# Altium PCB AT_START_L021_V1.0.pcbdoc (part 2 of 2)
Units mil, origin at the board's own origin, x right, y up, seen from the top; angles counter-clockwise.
Board outline 12992.58 x 3605 mil, 2 copper layers (Top Layer, Bottom Layer); 116 components, 109 nets, 471 pads, 502 vias.
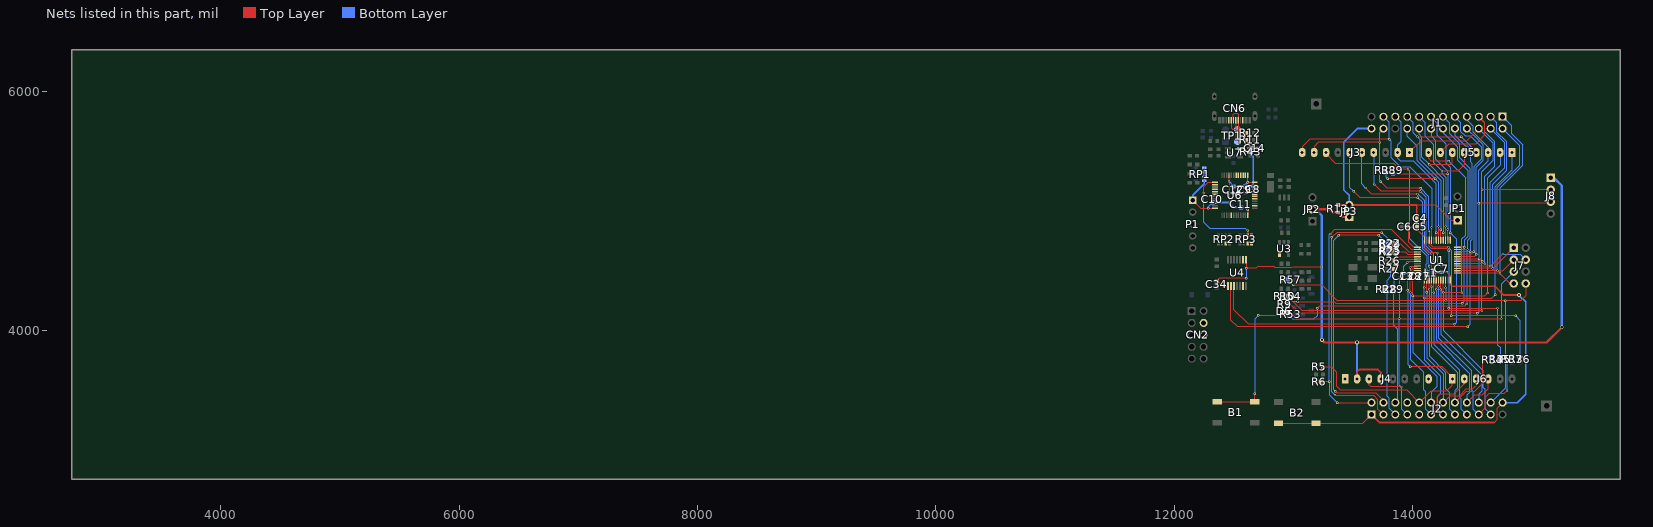
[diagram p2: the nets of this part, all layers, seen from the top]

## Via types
v1: diameter 19.68, hole 11.81, Top Layer to Bottom Layer, 217 vias
v2: diameter 19.7, hole 11.8, Top Layer to Bottom Layer, 181 vias
v3: diameter 19.7, hole 11.81, Top Layer to Bottom Layer, 91 vias
v4: diameter 31.5, hole 19.68, Top Layer to Bottom Layer, 13 vias

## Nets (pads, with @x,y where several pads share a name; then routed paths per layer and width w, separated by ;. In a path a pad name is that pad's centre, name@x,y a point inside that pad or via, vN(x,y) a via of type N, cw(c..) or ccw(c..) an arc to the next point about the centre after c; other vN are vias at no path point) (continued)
M_ATLK_SWO: RP3.6 U6.13 | length 844
  Top Layer w6: v1(12246.58,5152) 12246.58,5203 12285.12,5241.55 U6.13@12341.38,5241.55 ; RP3.6@12615.33,4798.44 12615.33,4837.75 v1(12615.58,4838)
  Bottom Layer w6: v1(12246.58,5152) 12246.58,4907 12300.58,4853 12600.58,4853 v1(12615.58,4838)
NRST: B1.1 B1.2 C13.2 D6.2 J2.7 J4.3 J7.5 U1.7 | length 5323.3
  Top Layer w6: B1.1@12360.5,3401.18 B1.2@12675.45,3401.18 12675.45,3467.12 v1(12674.58,3468) ; v1(12705.58,4126) 12905.58,4126 12941.58,4162 D6.2@12949.58,4162 12962.58,4162 13026.58,4098 13887.58,4098 v1(13888.58,4099) v1(14745.58,4099) ; J4.3@13633.35,3592.35 13633.35,3544.23 13652.58,3525 v1(13904.58,3525) ; v1(13955.58,4569) 13965.38,4578.8 U1.7@14039.67,4578.8
  Bottom Layer w6: v1(12674.58,3468) 12674.58,4095 v1(12705.58,4126) ; v1(13888.58,4099) 13888.58,4093.29 v1@13889.58,4092.29 ; J2.7@13954.61,3293.91 13904.58,3343.94 v1(13904.58,3525) 13889.58,3540 v1@13889.58,4092.29 ; v1(13955.58,4569) 13920.58,4534 C13.2@13920.58,4480.56 13889.58,4449.56 v1@13889.58,4092.29 ; v1(14745.58,4099) 14745.58,4390.12 J7.5@14848.35,4492.9
PA0: J2.10 J6.1 R5.2 U1.10 | length 2687.3
  Top Layer w6: R5.2@13246.24,3693 13317.58,3693 13358.58,3652 13358.58,3534 13392.58,3500 13948.52,3500 J2.10@14054.61,3393.91 14154.69,3494 14287.58,3494 14333.33,3539.76 J6.1@14333.33,3592.35 14333.33,3608.24 14246.58,3695 v1(13978.58,3695) ; v1(13957.58,4336) 13957.58,4472 14005.27,4519.7 U1.10@14039.67,4519.7
  Bottom Layer w6: v1(13957.58,4336) 13957.58,3716 v1(13978.58,3695)
PA1: J2.11 J6.2 U1.11 | length 1803.1
  Top Layer w6: v1(13981.58,4315) 13981.58,4475 14006.58,4500 U1.11@14039.67,4500 ; J2.11@14154.61,3293.91 14205.58,3344.88 14205.58,3442 14232.58,3469 14348.58,3469 14433.33,3553.76 J6.2@14433.33,3592.35
  Bottom Layer w6: v1(13981.58,4315) 13981.58,3759 14087.58,3653 14087.58,3506 14104.58,3489 14104.58,3343.94 J2.11@14154.61,3293.91
PA2: J2.12 J5.2 U1.12 | length 3078.3
  Top Layer w6: U1.12@14039.67,4480.3 14015.88,4480.3 14001.58,4466 v1(14001.58,4290) 14605.24,4290 v3(14628.58,4313.33)
  Bottom Layer w6: v1(14001.58,4290) 14001.58,3815 14202.58,3614 14202.58,3528 14154.61,3480.03 J2.12@14154.61,3393.91 ; v3(14628.58,4313.33) 14628.58,5280 14733.35,5384.78 J5.2@14733.35,5492.35
PA3: J2.13 J5.1 U1.13 | length 3072
  Top Layer w6: v3(14098.58,4271) 14664.58,4271 v1(14691.58,4298) ; v1(14098.58,4359) 14098.67,4359.1 U1.13@14098.67,4421.3
  Bottom Layer w6: v1(14098.58,4359) v3(14098.58,4271) 14098.58,3753 14231.58,3620 14231.58,3468 14204.58,3441 14204.58,3343.94 J2.13@14254.61,3293.91 ; v1(14691.58,4298) 14691.73,4297.84 14691.73,5206.16 14833.35,5347.78 J5.1@14833.35,5492.35
PA4: J2.14 J6.3 U1.14 | length 1476.8
  Top Layer w6: v1(14117.58,4319) 14118.38,4319.8 U1.14@14118.38,4421.3 ; J2.14@14254.61,3393.91 14309.69,3449 14389.98,3449 14449.63,3508.65 14503.23,3508.65 14533.33,3538.76 J6.3@14533.33,3592.35
  Bottom Layer w6: v1(14117.58,4319) 14117.58,3771 14254.61,3633.97 J2.14@14254.61,3393.91
PA5: J2.15 J3.6 U1.15 | length 2848
  Top Layer w6: v1(13504.58,5167) 13558.58,5113 v1(14043.58,5113) ; v1(14137.58,4342) 14138.08,4342.5 U1.15@14138.08,4421.3 14138.08,4537.5 v1(14137.58,4538)
  Bottom Layer w6: J3.6@13473.35,5492.35 13473.35,5198.23 v1(13504.58,5167) ; v1(14043.58,5113) 14083.58,5073 14083.58,4685 14137.58,4631 v1(14137.58,4538) ; v1(14137.58,4342) 14137.58,3786 14273.58,3650 14273.58,3514 14305.58,3482 14305.58,3342.94 J2.15@14354.61,3293.91
PA6: J2.16 J3.5 R34.1 U1.16 | length 3250.7
  Top Layer w6: v1(13607.58,5194) 13658.58,5143 v1(14040.58,5143) ; v1(14157.58,4365) 14157.77,4365.2 U1.16@14157.77,4421.3 14157.77,4559.8 v1(14157.58,4560) ; J2.16@14354.61,3393.91 14444.69,3484 14517.58,3484 14584.58,3551 14584.58,3730 v1(14619.58,3765)
  Bottom Layer w6: J3.5@13573.35,5492.35 13573.35,5228.23 v1(13607.58,5194) ; v1(14040.58,5143) 14048.58,5143 14098.58,5093 14098.58,4696 14157.58,4637 v1(14157.58,4560) ; v1(14157.58,4365) 14157.58,3868 14375.58,3650 14375.58,3512.55 14354.61,3491.58 J2.16@14354.61,3393.91 ; v1(14619.58,3765) 14639.24,3784.66 R34.1@14670.58,3784.66
PA7: J2.17 J3.4 U1.17 | length 2715
  Top Layer w6: v1(13677.58,5224) 13736.58,5165 v1(14064.58,5165) ; v1(14176.58,4318) 14177.48,4318.9 U1.17@14177.48,4421.3 14177.48,4582.9 v1(14177.58,4583)
  Bottom Layer w6: J3.4@13673.35,5492.35 13677.58,5488.13 v1(13677.58,5224) ; v1(14064.58,5165) 14114.58,5115 14114.58,4706 14177.58,4643 v1(14177.58,4583) ; v1(14176.58,4318) 14176.58,3885 14392.58,3669 14392.58,3442 14404.58,3430 14404.58,3343.94 J2.17@14454.61,3293.91
PA8: J1.5 J5.7 U1.29 | length 2160.1
  Top Layer w6: J5.7@14233.35,5492.35 14304,5563 14527.58,5563 14601.58,5637 14601.58,5745.12 J1.5@14554.6,5792.09 ; U1.29@14374.27,4559.1 14606.48,4559.1 v1(14606.58,4559)
  Bottom Layer w6: J1.5@14554.6,5792.09 14605.58,5741.12 14605.58,5665 14689.58,5581 14689.58,5377 14604.58,5292 14604.58,4561 v1(14606.58,4559)
PA9: J1.6 J3.1 J8.2 R10.2 U1.30 | length 4743.9
  Top Layer w6: R10.2@12955.58,4283 13073.58,4165 v1(14581.58,4165) ; J3.1@13973.35,5492.35 14065.99,5585 14447.5,5585 J1.6@14554.6,5692.09 ; U1.30@14374.27,4578.8 14582.38,4578.8 v1(14582.58,4579) ; v1(14581.58,5179) J8.2@15158.58,5179
  Bottom Layer w6: J1.6@14554.6,5692.09 14676.58,5570.12 14676.58,5427 14580.58,5331 v1@14580.58,5178.87 ; v1(14581.58,4165) 14581.58,4578 v1(14582.58,4579) 14580.58,4581 v1@14580.58,5178.87 ; v1(14581.58,5179) 14580.7,5179 v1@14580.58,5178.87
PA10: J1.7 J5.3 J8.3 R9.2 U1.31 | length 4178
  Top Layer w6: R9.2@12955.24,4220 12974.58,4220 13052.58,4142 v1(14541.58,4142) ; U1.31@14374.27,4598.4 14556.98,4598.4 v1(14557.58,4599) ; v1(14553.58,5066) 15145.58,5066 J8.3@15158.58,5079
  Bottom Layer w6: J1.7@14454.6,5792.09 14454.6,5765.98 14505.58,5715 14505.58,5664 14552.58,5617 14552.58,5615.5 14633.35,5534.72 J5.3@14633.35,5492.35 14633.35,5422.78 14553.58,5343 v1(14553.58,5066) 14557.58,5062 v1(14557.58,4599) 14557.58,4158 v1(14541.58,4142)
PA11: J1.8 U1.32 | length 1302.7
  Top Layer w6: U1.32@14374.27,4618.1 14515.67,4618.1 v1(14534.58,4637)
  Bottom Layer w6: J1.8@14454.6,5692.09 14548.58,5598.12 14548.58,5597 14590.58,5555 14590.58,5426 14534.73,5370.16 14534.73,4637.16 v1(14534.58,4637)
PA12: J1.9 U1.33 | length 1425.2
  Top Layer w6: U1.33@14374.27,4637.8 14492.38,4637.8 v1(14512.58,4658)
  Bottom Layer w6: J1.9@14354.6,5792.09 14403.58,5743.12 14403.58,5668 14444.58,5627 14487.58,5627 14577.58,5537 14577.58,5440 14515.58,5378 14515.58,4661 v1(14512.58,4658)
PA13/SWDIO: J1.10 U1.34 U4.2 | length 4152.1
  Top Layer w6: U4.2@12475.4,4371.76 12475.4,4086.18 12531.58,4030 v1(14463.58,4030) ; U1.34@14374.27,4657.5 14481.08,4657.5 v1(14482.58,4659)
  Bottom Layer w6: J1.10@14354.6,5692.09 14354.6,5634.98 14440.12,5549.45 14457.12,5549.45 14482.58,5524 14482.58,5418 14497.58,5403 14497.58,4761.4 14482.58,4746.4 v1(14482.58,4659) 14483.58,4658 14483.58,4050 v1(14463.58,4030)
PA14/SWCLK: J1.13 U1.37 U4.3 | length 3999.9
  Top Layer w6: U4.3@12500.99,4371.76 12500.99,4173.59 12624.58,4050 v1(14351.58,4050) ; U1.37@14315.27,4755.9 14315.27,4818.7 v1(14315.58,4819)
  Bottom Layer w6: J1.13@14154.6,5792.09 14203.58,5743.12 14203.58,5641 14277.58,5567 14277.58,5405 14315.58,5367 v1(14315.58,4819) 14316.58,4819 14366.58,4769 14366.58,4065 v1(14351.58,4050)
PA15: J1.14 R39.1 U1.38 | length 1456.1
  Top Layer w6: v1(13886.58,5312) v1(14295.58,5312) ; U1.38@14295.58,4755.9 v1(14295.58,4846)
  Bottom Layer w6: R39.1@13834.58,5313.34 13885.24,5313.34 v1(13886.58,5312) ; J1.14@14154.6,5692.09 14154.6,5632.09 14191.58,5595.11 14191.58,5439 14295.58,5335 v1(14295.58,5312) v1(14295.58,4846)
PB0: J2.18 J6.4 U1.18 | length 1461.2
  Top Layer w6: v1(14196.58,4342) 14197.17,4342.6 U1.18@14197.17,4421.3 ; J2.18@14454.61,3393.91 14520.69,3460 14583.58,3460 14633.33,3509.76 J6.4@14633.33,3592.35
  Bottom Layer w6: v1(14196.58,4342) 14196.58,3919 14475.58,3640 14475.58,3476.24 14454.61,3455.28 J2.18@14454.61,3393.91
PB1: J2.19 R37.1 U1.19 | length 1950.6
  Top Layer w6: v1(14216.58,4365) 14216.77,4365.2 U1.19@14216.77,4421.3 ; J2.19@14554.61,3293.91 14606.58,3345.88 14606.58,3436 14636.58,3466 14764.58,3466 v1(14791.58,3493)
  Bottom Layer w6: v1(14216.58,4365) 14216.58,3939 14489.58,3666 14489.58,3502 14504.58,3487 14504.58,3343.94 J2.19@14554.61,3293.91 ; v1(14791.58,3493) 14791.58,3741.66 R37.1@14835.58,3785.66
PB2: J2.20 U1.20 | length 1178.3
  Top Layer w6: U1.20@14236.48,4421.3 14236.48,4342.1 v1(14236.58,4342)
  Bottom Layer w6: v1(14236.58,4342) 14236.42,4341.84 14236.42,3968.16 14577.58,3627 14577.58,3488 14554.61,3465.03 J2.20@14554.61,3393.91
PB3: J1.15 J5.5 U1.39 | length 1441.2
  Top Layer w6: v1(14245.58,5337) 14382.58,5337 14433.35,5387.78 J5.5@14433.35,5492.35 ; v1(14275.58,4871) 14275.88,4870.7 U1.39@14275.88,4755.9
  Bottom Layer w6: J1.15@14054.6,5792.09 14104.58,5742.12 14104.58,5630 14177.58,5557 14177.58,5405 v1(14245.58,5337) 14245.58,5316 14275.58,5286 v1(14275.58,4871)
PB4: J1.16 J5.6 U1.40 | length 1306.8
  Top Layer w6: v3(14137.58,5392) 14317.47,5392 14332.58,5407.11 14332.58,5491.58 J5.6@14333.35,5492.35 ; U1.40@14256.17,4755.9 14256.17,4819.6 v1(14256.58,4820)
  Bottom Layer w6: J1.16@14054.6,5692.09 14054.6,5642.98 14077.58,5620 14077.58,5452 v3(14137.58,5392) 14256.58,5273 v1(14256.58,4820)
PB5: J1.17 J5.4 U1.41 | length 1703
  Top Layer w6: v1(14040.58,5623) v1(14408.58,5623) ; U1.41@14236.48,4755.9 14236.48,4843.9 v1(14236.58,4844)
  Bottom Layer w6: J1.17@13954.6,5792.09 14003.58,5743.12 14003.58,5659 v1@14039.58,5623 ; v1(14040.58,5623) 14060.58,5603 14060.58,5436 14236.58,5260 v1(14236.58,4844) ; v1(14408.58,5623) 14533.35,5498.22 J5.4@14533.35,5492.35
PB6: J1.18 R38.2 U1.42 | length 1502
  Top Layer w6: v1(13790.58,5272) v1(14190.58,5272) ; v1(14216.58,4871) 14216.77,4870.8 U1.42@14216.77,4755.9
  Bottom Layer w6: R38.2@13772.58,5321.72 13772.58,5290 v1(13790.58,5272) ; J1.18@13954.6,5692.09 13954.6,5627.98 14039.58,5543 14039.58,5423 v1(14190.58,5272) 14216.58,5246 v1(14216.58,4871)
PB7: J1.19 J3.2 U1.43 | length 1267.1
  Top Layer w6: U1.43@14197.17,4755.9 14197.17,4819.6 v1(14197.58,4820)
  Bottom Layer w6: J1.19@13854.6,5792.09 13902.58,5744.12 13902.58,5585 13873.35,5555.77 J3.2@13873.35,5492.35 13873.35,5444.23 13899.58,5418 14009.58,5418 14197.58,5230 v1(14197.58,4820)
PB8: J1.21 J3.10 R36.1 U1.45 | length 3728.6
  Top Layer w6: J3.10@13073.35,5492.35 13073.35,5541.77 13135.58,5604 v1(13802.58,5604) ; v1(14158.58,4863) 14157.77,4862.2 U1.45@14157.77,4755.9 14157.77,4714.8 14174.58,4698 14299.58,4698 v1(14300.58,4697) ; v1(14324.58,4121) v1(14863.58,4121)
  Bottom Layer w6: J1.21@13754.6,5792.09 13802.58,5744.12 v1(13802.58,5604) 13816.58,5590 13816.58,5453 13896.58,5373 13975.58,5373 14158.58,5190 v1(14158.58,4863) ; v1(14300.58,4697) 14324.58,4673 v1(14324.58,4121) ; v1(14863.58,4121) 14899.58,4085 R36.1@14899.58,3778.12
PB9: J1.22 J3.9 R35.1 U1.46 | length 3433.4
  Top Layer w6: J3.9@13173.35,5492.35 13173.35,5539.77 13209.85,5576.28 v3(13722.58,5576.28) ; v1(13733.58,5247) 13788.58,5192 v1(14066.58,5192) ; v1(14136.58,4834) 14138.08,4832.5 U1.46@14138.08,4755.9 14138.08,4705.5 14159.58,4684 14286.58,4684 v1(14302.58,4668) ; v1(14303.58,4186) 14710.58,4186 v1(14711.58,4185)
  Bottom Layer w6: v1(13733.58,5247) 13722.58,5258 v3(13722.58,5576.28) 13722.58,5660.07 J1.22@13754.6,5692.09 ; v1(14066.58,5192) 14136.58,5122 v1(14136.58,4834) ; v1(14302.58,4668) 14303.58,4667 v1(14303.58,4186) ; v1(14711.58,4185) 14711.58,3881 14733.58,3859 R35.1@14733.58,3778.12
PB10: J2.21 J5.8 U1.21 | length 2854.3
  Top Layer w6: J5.8@14133.35,5492.35 14133.35,5444.22 14157.58,5420 v1(14303.58,5420) ; U1.21@14256.17,4421.3 14256.17,4317.4 v1(14256.58,4317) 14257.58,4316 v1(14413.58,4316)
  Bottom Layer w6: v1(14256.58,4317) 14256.58,3999 14589.58,3666 14589.58,3522 14603.58,3508 14603.58,3344.94 J2.21@14654.61,3293.91 ; v1(14303.58,5420) 14444.58,5279 14444.58,4799 14412.58,4767 14412.58,4317 v1(14413.58,4316)
PB11: J2.22 J7.8 R57.1 U1.22 | length 3270.3
  Top Layer w6: v1(12997.58,4381) 13237.74,4381 13368.74,4250 v3(14276.58,4250) 14775.58,4250 v1(14776.58,4249) 14777.58,4250 14907.58,4250 14948.35,4290.78 J7.8@14948.35,4392.9 ; v1(14275.58,4356) 14275.88,4356.3 U1.22@14275.88,4421.3
  Bottom Layer w6: R57.1@12948.92,4425 12992.92,4381 v1(12997.58,4381) ; v1(14275.58,4356) 14276.58,4355 v3(14276.58,4250) ; J2.22@14654.61,3393.91 14656.49,3393.91 14776.58,3514 v1(14776.58,4249)
PB12: J1.1 J7.7 U1.25 | length 1969.8
  Top Layer w6: U1.25@14374.27,4480.3 14732.27,4480.3 v1(14732.58,4480) 14819.68,4392.9 J7.7@14848.35,4392.9
  Bottom Layer w6: v1(14732.58,4480) 14733.58,4481 14733.58,5197 14921.58,5385 14921.58,5557.86 14825.36,5654.07 14825.36,5721.33 J1.1@14754.6,5792.09
PB13: J1.2 J7.3 U1.26 | length 1840.7
  Top Layer w6: U1.26@14374.27,4500 v1(14711.58,4500) 14756.58,4500 14848.35,4591.78 J7.3@14848.35,4592.9
  Bottom Layer w6: v1(14711.58,4500) 14711.58,5200 14896.58,5385 14896.58,5550.12 J1.2@14754.6,5692.09
PB14: J1.3 J7.1 U1.27 | length 1924.1
  Top Layer w6: U1.27@14374.27,4519.7 v1@14669.87,4519.7 ; v1(14670.58,4519) v1@14669.87,4519.7 ; J7.1@14848.35,4692.9 14848.35,4691.78 14676.27,4519.7 v1@14669.87,4519.7
  Bottom Layer w6: J1.3@14654.6,5792.09 14705.58,5741.12 14705.58,5662 14787.58,5580 14787.58,5342 14670.58,5225 v1(14670.58,4519)
PB15: J1.4 J7.4 U1.28 | length 1888
  Top Layer w6: U1.28@14374.27,4539.4 14648.98,4539.4 14749.58,4640 v1(14757.58,4640)
  Bottom Layer w6: v1(14649.58,4540) 14649.58,5242 14773.58,5366 14773.58,5573.12 J1.4@14654.6,5692.09 ; v1(14757.58,4640) 14901.25,4640 J7.4@14948.35,4592.9
PC13: J2.2 R6.2 U1.2 | length 2611.1
  Top Layer w6: R6.2@13236.85,3570 13299.58,3570 v1(13301.58,3568) ; v1(13308.58,4808) 13343.58,4843 13826.58,4843 13992.38,4677.2 U1.2@14039.67,4677.2 ; v2(13367.66,3393.91) J2.2@13654.61,3393.91
  Bottom Layer w6: v1(13308.58,4808) 13301.58,4801 v1(13301.58,3568) 13301.58,3460 v2(13367.66,3393.91)
PC14: J2.3 R24.2 | length 2404.2
  Top Layer w6: v3(13322.58,4781) 13361.58,4820 v3(13740.58,4820) ; v1(13348.58,3457) 13671.58,3457 13704.58,3424 13704.58,3343.94 J2.3@13754.61,3293.91
  Bottom Layer w6: v3(13322.58,4781) 13322.58,3483 v1(13348.58,3457) ; v3(13740.58,4820) 13793.3,4767.28 R24.2@13793.3,4727
PC14/LEXT_IN: R22.2 R24.1 U1.3 | length 269.2
  Top Layer w6: R22.2@13837.24,4732 v1(13871.58,4732) 13893.58,4732 13968.08,4657.5 U1.3@14039.67,4657.5
  Bottom Layer w6: R24.1@13837.69,4727 13866.58,4727 v1(13871.58,4732)
PC15: J2.4 R25.2 | length 2299.1
  Top Layer w6: v1(13350.58,3489) 13361.58,3478 13689.58,3478 13754.61,3412.97 J2.4@13754.61,3393.91 ; v3(13378.58,4797) 13380.58,4799 v3(13716.58,4799)
  Bottom Layer w6: v1(13350.58,3489) 13337.58,3502 13337.58,4756 v3(13378.58,4797) ; v3(13716.58,4799) 13741.58,4774 13741.58,4698 13773.58,4666 R25.2@13792.3,4666
PC15/LEXT_OUT: R23.2 R25.1 U1.4 | length 251.4
  Top Layer w6: R23.2@13838.24,4660 13839.24,4661 v3(13874.58,4661) 13936.58,4661 13959.77,4637.8 U1.4@14039.67,4637.8
  Bottom Layer w6: R25.1@13836.69,4666 13841.69,4661 v3(13874.58,4661)
PF0: J2.5 R28.2 | length 1060.5
  Bottom Layer w6: R28.2@13780.58,4323.72 13783.58,4320.72 13783.58,3450 13802.58,3431 13802.58,3345.94 J2.5@13854.61,3293.91
PF0/HEXT_IN: R26.2 R28.1 U1.5 | length 456.5
  Top Layer w6: v1(13811.58,4554) 13837.24,4579.66 R26.2@13837.24,4585 13870.33,4618.1 U1.5@14039.67,4618.1
  Bottom Layer w6: R28.1@13780.58,4368.12 13780.58,4417 13811.58,4448 v1(13811.58,4554)
PF1: J2.6 R29.2 | length 955.1
  Bottom Layer w6: R29.2@13837.58,4323.72 13837.58,4048.68 13876.58,4009.68 13876.58,3415.88 J2.6@13854.61,3393.91
PF1/HEXT_OUT: R27.2 R29.1 U1.6 | length 403.7
  Top Layer w6: v1(13839.58,4464) 13839.24,4464.34 R27.2@13839.24,4515 13871.58,4547.34 13871.58,4583 13886.98,4598.4 U1.6@14039.67,4598.4
  Bottom Layer w6: R29.1@13837.58,4368.12 13839.58,4370.12 v1(13839.58,4464)
PF6: J1.11 R53.1 U1.35 | length 3373.4
  Top Layer w6: v1(13198.58,4186) 13219.58,4207 14439.58,4207 v1(14453.58,4221) ; U1.35@14374.27,4677.2 14458.77,4677.2 v1(14459.58,4678)
  Bottom Layer w6: R53.1@12949.47,4136 12993.47,4092 13167.58,4092 13198.58,4123 v1(13198.58,4186) ; J1.11@14254.6,5792.09 14305.58,5741.12 14305.58,5654 14389.58,5570 14389.58,5450 14479.58,5360 14479.58,4772 14459.58,4752 v1(14459.58,4678) 14459.58,4227 v1(14453.58,4221)
PF7: J1.12 R54.1 U1.36 | length 3120.3
  Top Layer w6: v1(13033.58,4240) 13343.38,4240 13355.38,4228 v1(14416.58,4228) ; U1.36@14374.27,4696.9 14433.48,4696.9 v1(14433.58,4697)
  Bottom Layer w6: R54.1@12948.92,4286 12994.92,4240 v1(13033.58,4240) ; J1.12@14254.6,5692.09 14254.6,5658.98 14374.58,5539 14374.58,5433 14462.58,5345 14462.58,4783.04 14433.58,4754.04 v1(14433.58,4697) 14433.58,4245 v1(14416.58,4228)
USB+: CN6.A6 CN6.B6 R11.1 TP1.3 | length 393.3
  Top Layer w6: CN6.B6@12477.08,5761.7 12477.08,5701.5 12491.5,5687.08 12516.38,5687.08 ; CN6.A6@12516.38,5761.7 12516.38,5687.08 ; R11.1@12606.92,5597 v3(12572.09,5597) 12541.58,5597 12516.38,5622.2 12516.38,5687.08
  Bottom Layer w6: TP1.3@12530.58,5583 12544.58,5597 v3(12572.09,5597)
USB-: CN6.A7 CN6.B7 R12.1 TP1.2 | length 368.2
  Top Layer w6: CN6.A7@12496.77,5761.7 12496.77,5812.2 12506.58,5822 12526.58,5822 12536.08,5812.5 CN6.B7@12536.08,5761.7 12536.08,5672.5 12551.58,5657 v3(12572.97,5657) R12.1@12606.92,5657
  Bottom Layer w6: TP1.2@12530.58,5683 12556.58,5657 v3(12572.97,5657)
VCC: C8.2 C9.2 C10.2 C11.2 C12.2 C14.2 P1.1 R43.2 RP1.1 RP1.2 RP1.3 RP1.4 U6.1 U6.9 U6.24 U6.36 U6.48 U7.5 | length 2036.1
  Top Layer w10: P1.1@12154.58,5092 12221.58,5025 v1(12284.58,5025) U6.24@12341.38,5025.01 ; U6.9@12459.49,5300.6 12459.49,5251.08 v1(12459.58,5251) v1(12459.58,5072) ; v1(12616.58,5012) 12616.97,5011.6 U6.36@12616.97,4965.95 ; U6.1@12616.97,5300.6 12616.97,5242.4 v1(12616.58,5242) 12675.58,5242 U6.48@12676.03,5241.55
  Top Layer w15: U7.5@12551.58,5527 v4(12599.44,5527) 12641.24,5527 R43.2@12641.58,5526.66
  Bottom Layer w10: v1(12284.58,5025) 12284.58,5036.44 C10.2@12320.58,5072.44 ; v1@12458.72,5072.44 12459.16,5072 v1(12459.58,5072) ; v1(12459.58,5251) 12495.58,5215 C12.2@12495.58,5207.56
  Bottom Layer w15: P1.1@12154.58,5092 12154.58,5134 12251.58,5231 RP1.4@12251.58,5255.7 RP1.3@12251.58,5291.13 RP1.2@12251.58,5326.57 RP1.1@12251.58,5362 ; C10.2@12320.58,5072.44 12458.72,5072.44 12458.72,5071.85 12499.14,5031.44 C11.2@12559.58,5031.44 12597.14,5031.44 v1(12616.58,5012) ; C12.2@12495.58,5207.56 C9.2@12592.58,5207.56 ; v4(12599.44,5527) C14.2@12649.01,5527 12649.01,5473.65 12662.58,5460.09 C8.2@12662.58,5209.56 12660.58,5207.56 C9.2@12592.58,5207.56 ; v1(12616.58,5242) 12592.58,5218 C9.2@12592.58,5207.56
VDD: B2.1 B2.2 C4.2 C5.2 C6.2 C7.2 J1.24 J2.1 J2.24 JP1.1 JP3.2 L1.1 R13.2 U1.1 U1.24 U1.48 | length 6855.7
  Top Layer w6: B2.2@12874.5,3222.03 B2.1@13189.45,3222.03 13582.72,3222.03 J2.1@13654.61,3293.91
  Top Layer w10: C4.2@14034.01,4941 14034.01,4873 C5.2@14036.01,4871 ; 14034.01,5051 14196.58,5051 14326.58,4921 14374.58,4921 JP1.1@14376.59,4923 ; U1.1@14039.67,4696.9 14008.67,4696.9 13961.14,4744.44 C6.2@13961.14,4870 14035.01,4870 C5.2@14036.01,4871 ; v1(14205.58,4649) 14140.58,4649 14098.67,4690.9 U1.48@14098.67,4755.9 14098.67,4783.9 14036.01,4846.56 C5.2@14036.01,4871 ; v1(14284.58,4489) 14315.27,4458.3 U1.24@14315.27,4421.3 14315.27,4383.3 14328.58,4370 ; 14659.58,4370 14661.58,4368 ; 14682.58,3226 14704.58,3248 14704.58,3343.88 J2.24@14754.61,3393.91
  Top Layer w15: R13.2@13373.58,5050.66 13467.24,5050.66 JP3.2@13467.58,5051 14034.01,5051 C4.2@14034.01,4941 ; J2.1@13654.61,3293.91 13722.52,3226 14682.58,3226 ; 14328.58,4370 14659.58,4370 14690.58,4370 14764.58,4296 v4(14891.58,4296)
  Bottom Layer w10: v1(14205.58,4649) 14205.58,4556 14179.17,4529.6 L1.1@14179.17,4485 C7.2@14253.94,4485 ; C7.2@14249.58,4487.44 14283.01,4487.44 v1(14284.58,4489)
  Bottom Layer w15: JP3.2@13467.58,5051 13467.58,5132 13422.58,5177 13422.58,5578 13536.67,5692.09 J1.24@13654.6,5692.09 ; J2.24@14754.61,3393.91 14755.52,3393 14878.58,3393 14948.58,3463 14948.58,4239 v4(14891.58,4296)
VDD_MCU: C34.2 J4.2 J4.4 J8.1 JP2.2 JP3.1 R13.1 U4.1 U4.8 | length 6682.3
  Top Layer w6: v1(12603.58,4520) 12684.58,4520 12703.58,4539 12832.76,4539 12848.76,4523 12986.58,4523 12994.58,4531 v1(13238.58,4531)
  Top Layer w10: U4.1@12449.81,4371.76 12402.82,4371.76 12359.01,4415.56 C34.2@12355.58,4415.56 12377.01,4437 v1(12603.58,4437) ; U4.8@12603.34,4592.24 12603.34,4520.23 v1(12603.58,4520)
  Top Layer w15: R13.1@13373.58,4985 R13.1@13373.58,4991.34 ; J4.2@13533.35,3592.35 13533.35,3651.77 13552.58,3671 13708.58,3671 13733.35,3646.23 J4.4@13733.35,3592.35
  Top Layer w20: JP2.2@13159.59,5015 13300.58,5015 13326.58,4989 13369.58,4989 13373.58,4985 13378.58,4985 13412.58,4951 JP3.1@13467.58,4951 ; v4(13239.58,3920) 13261.58,3898 v4@13534.06,3898 ; v4(13533.58,3899) 13534.06,3898.52 v4@13534.06,3898 ; v4(15251.58,4026) 15123.58,3898 v4@13534.06,3898
  Bottom Layer w10: v1(12603.58,4437) v1(12603.58,4520)
  Bottom Layer w20: JP2.2@13159.59,5015 13184.58,5015 13238.58,4961 v1(13238.58,4531) 13238.58,3920.4 13239.18,3920.4 v4(13239.58,3920) ; J4.2@13533.35,3592.35 13533.35,3898.77 v4(13533.58,3899) ; J8.1@15158.58,5279 15185.58,5279 15251.58,5213 v4(15251.58,4026)
VDDA: C27.2 C28.2 J3.8 L1.2 U1.9 | length 1944.9
  Top Layer w10: J3.8@13273.35,5492.35 13273.35,5482.23 13356.58,5399 13844.58,5399 13892.58,5351 v1(13960.58,5351) ; v1(13980.58,4527) 13992.98,4539.4 U1.9@14039.67,4539.4
  Bottom Layer w10: v1(13960.58,5351) 13974.58,5337 13974.58,4769 14122.58,4621 14122.58,4563 14112.58,4553 14112.58,4523 14123.98,4511.6 L1.2@14123.98,4485 14120.53,4481.56 C27.2@14057.58,4481.56 14056.58,4480.56 C28.2@13988.58,4480.56 13980.58,4488.56 v1(13980.58,4527)
"": CN2.4 CN2.6 CN6.A8 CN6.B8 J2.8 J2.9 J4.1 J4.8 RP2.3 RP3.3 RP3.4 RP3.5 U3.4 U4.6 U4.9 U6.2 U6.3 U6.4 U6.5 U6.6 U6.14 U6.15 U6.16 U6.17 U6.18 U6.21 U6.22 U6.29 U6.38 U6.41 U6.42 U6.43 U6.45 U6.46

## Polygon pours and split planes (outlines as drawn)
GND on Bottom Layer (solid, remove dead copper, pour order 0): 11982.58,3017 15492.58,3017 15492.58,6105 11982.58,6105
GND on Top Layer (solid, remove dead copper, pour order 1): 11965.58,3000 15485.58,3000 15485.58,6088 11965.58,6088

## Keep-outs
Top Layer:
  region net "": 12569.55,5711.64 12623.55,5711.64 12623.55,5728.64 12569.55,5728.64
Board Outline Layer:
  lines w8 net "": 12006.57,3110.74 ccw(c12085.32,3110.74) 12085.32,3032 15392.4,3032 ccw(c15392.4,3110.74) 15471.14,3110.74 15471.14,5984.76 ccw(c15392.4,5984.76) 15392.4,6063.5 12085.32,6063.5 ccw(c12085.32,5984.76) 12006.57,5984.76 ; 12006.58,3110.74 12006.58,5984.76
Multi-Layer:
  region net "": 15384.57,5929.2 ccw(c15321.57,5929.2) 15258.58,5929.2 ccw(c15321.57,5929.2)
  region net "": 15384.57,3154.52 ccw(c15321.57,3154.52) 15258.58,3154.52 ccw(c15321.57,3154.52)
  region net "": 12193.58,3154.52 ccw(c12130.59,3154.23) 12067.6,3154.52 ccw(c12130.59,3154.81)
  region net "": 12193.58,5929.2 ccw(c12130.59,5928.92) 12067.6,5929.2 ccw(c12130.59,5929.49)
  region net "": 14996.34,4892.35 ccw(c14933.34,4892.35) 14870.35,4892.35 ccw(c14933.34,4892.35)
  region net "": 12946.34,3592.35 ccw(c12883.34,3592.35) 12820.35,3592.35 ccw(c12883.34,3592.35)
  region net "": 12996.34,5492.35 ccw(c12933.34,5492.35) 12870.35,5492.35 ccw(c12933.34,5492.35)

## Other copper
Top Layer:
  drawing of 490 lines, arcs and shapes, not listed
Bottom Layer:
  drawing of 339 lines, arcs and shapes, not listed

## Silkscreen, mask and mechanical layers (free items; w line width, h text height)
Top Silkscreen Layer:
  lines w5 net "": 14711.98,5354.6 14713.98,5354.6 ; 14852.98,5369.6 14850.98,5369.6 ; 14713.98,5354.6 14732.98,5373.6 14732.98,5378.6 ; 14713.98,5354.6 14749.98,5354.6 ; 14713.98,5354.6 14715.98,5354.6 14732.98,5371.6 ; 14732.98,5354.6 14729.98,5357.6 14718.98,5357.6 14719.98,5356.6 14724.98,5356.6 14731.48,5363.1 14732.98,5363.1 14741.48,5354.6 14749.98,5354.6 ; 14732.98,5354.6 14732.98,5371.6 ; 14732.98,5354.6 14737.98,5359.6 ; 14732.98,5371.6 14737.98,5366.6 14737.98,5359.6 ; 14732.98,5371.6 14752.98,5351.6 ; 14732.98,5371.6 14732.98,5378.6 ; 14732.98,5378.6 14730.98,5378.6 14703.98,5351.6 14752.98,5351.6 ; 14732.98,5378.6 14759.98,5351.6 14752.98,5351.6 ; 14737.98,5359.6 14744.98,5359.6 14749.98,5354.6 ; 14749.98,5354.6 14752.98,5351.6 ; 14811.98,5372.6 14860.98,5372.6 14833.98,5345.6 14831.98,5345.6 ; 14811.98,5372.6 14804.98,5372.6 14831.98,5345.6 ; 14811.98,5372.6 14814.98,5369.6 ; 14811.98,5372.6 14831.98,5352.6 ; 14814.98,5369.6 14823.48,5369.6 14831.98,5361.1 14833.48,5361.1 14839.98,5367.6 14844.98,5367.6 14845.98,5366.6 14834.98,5366.6 14831.98,5369.6 ; 14814.98,5369.6 14819.98,5364.6 14826.98,5364.6 ; 14814.98,5369.6 14850.98,5369.6 ; 14826.98,5364.6 14831.98,5369.6 ; 14826.98,5364.6 14826.98,5357.6 14831.98,5352.6 ; 14831.98,5345.6 14831.98,5352.6 ; 14831.98,5345.6 14831.98,5350.6 14850.98,5369.6 ; 14831.98,5352.6 14831.98,5369.6 ; 14831.98,5352.6 14848.98,5369.6 14850.98,5369.6
  lines w8 net "": 12025.57,4197.63 12025.57,4121.63 12064.57,4160.63 12027.57,4197.63 ; 12088.57,3910.63 12048.57,3910.63 12048.57,4010.63 12089.57,4010.63 ; 12339.58,3829 12779.58,3829 ; 12339.58,3919 12779.58,3919 ; 12339.58,4009 12779.58,4009 ; 12339.58,4099 12779.58,4099 ; 12569.58,3739 12569.58,4189 ; 12339.58,3739 12779.58,3739 12779.58,4189 12339.58,4189 12339.58,3739
  lines w10 net "": 13459.57,5224.75 14875.27,5224.75 ; 13716.48,3885.6 14169.48,3885.6 ; 14327.98,3885.6 14887.98,3885.6
  text "35" at 14215.41,5979.76 h38.28
  text "25" at 14713.41,5979.76 h38.28
  text "47" at 13624.41,5977.76 h38.28
  text "B8" at 13745.24,5865.32 h34.45 r45
  text "B7" at 13851.24,5865.32 h34.45 r45
  text "B5" at 13946.92,5865.32 h34.45 r45
  text "B3" at 14043.18,5865.32 h34.45 r45
  text "F6" at 14241.13,5865.38 h34.45 r45
  text "B12" at 14738.95,5863.32 h34.45 r45
  text "A8" at 14538.24,5862.26 h34.45 r45
  text "A14" at 14125.95,5860.69 h34.45 r45
  text "A12" at 14331.98,5861.22 h34.45 r45
  text "A10" at 14429.95,5861.22 h34.45 r45
  text "B14" at 14632.95,5861.32 h34.45 r45
  text "GND" at 13633.47,5856.98 h34.45 r45
  text "GND" at 13123.65,5756.71 h45.94
  text "LD:" at 12030.28,5602.23 h46.73 r270
  text "B9" at 13740.24,5565.62 h34.45 r45
  text "F7" at 14247.14,5559.33 h34.45 r45
  text "A9" at 14546.24,5558.62 h34.45 r45
  text "B6" at 13938.93,5557.3 h34.45 r45
  text "B4" at 14036.2,5557.32 h34.45 r45
  text "B15" at 14643.95,5552.32 h34.45 r45
  text "A15" at 14138.95,5551.32 h34.45 r45
  text "A11" at 14439.73,5551.1 h34.45 r45
  text "B13" at 14745.16,5550.25 h34.45 r45
  text "A13" at 14336.95,5548.32 h34.45 r45
  text "BOOT0" at 13791.9,5542.27 h28.71 r30
  text "VDD" at 13616.95,5541.32 h34.45 r45
  text "1" at 12030.8,5479.3 h47.07 r270
  text "2" at 12029.8,5412.3 h47.07 r270
  text "1" at 14754.55,5398.76 h46.27 r90
  text "4" at 14450.2,5385.6 h45.56 r90
  text "2" at 14654.2,5385.6 h45.56 r90
  text "8" at 13999.27,5383 h45.56 r90
  text "7" at 14159.2,5382.6 h45.56 r90
  text "13" at 13499.38,5356.62 h45.94 r90
  text "12" at 13597.38,5356.62 h45.94 r90
  text "#6" at 14252.38,5339.92 h45.94 r90
  text "#5" at 14354.38,5339.92 h45.94 r90
  text "#9" at 13898.38,5338.92 h45.94 r90
  text "#3" at 14553.38,5338.92 h45.94 r90
  text "3" at 12028.8,5334.3 h47.07 r270
  text "#11" at 13699.38,5326.57 h45.94 r90
  text "#10" at 13798.38,5308.87 h45.94 r90
  text "SCL" at 13096.38,5293.67 h45.94 r90
  text "GND" at 13396.38,5289.27 h45.94 r90
  text "SDA" at 13198.38,5287.07 h45.94 r90
  text "VDD" at 14975.14,5258.75 h40.19
  text "TX" at 14752.38,5254.85 h45.94 r90
  text "4" at 12029.8,5254.3 h47.07 r270
  text "DIGITAL(#=PWM)" at 13855.59,5253.87 h40.19
  text "RX 0" at 14856.38,5248.82 h45.94 r90
  text "VDDA" at 13295.38,5237.22 h45.94 r90
  text "AT-Link-EZ V1.4" at 12026.22,5165.16 h57.42 r270
  text "USART1_TX" at 14738.55,5162.75 h40.19
  text "GND" at 14444.14,5107.75 h40.19
  text "USART1_RX" at 14737.55,5057.75 h40.19
  text "3.3V" at 13292.59,5043.96 h46.73 r90
  text "BOOT0" at 14442.61,5002.75 h40.19
  text "GND" at 14977.14,4960.75 h40.19
  text "IDD" at 13596.59,4953.01 h46.73 r90
  text "VDD" at 14448.14,4898.75 h40.19
  text "VDD_MCU" at 13069.59,4850.8 h46.73 r90
  text "1.8V" at 13288.59,4838.96 h46.73 r90
  text "5V" at 15033.38,4676.87 h40.19
  text "MISO" at 14627.42,4675.87 h40.19
  text "MOSI" at 15022.42,4574.87 h40.19
  text "SCK" at 14647.9,4572.87 h40.19
  text "GND" at 15022.9,4476.87 h40.19
  text "RESET" at 14596.61,4469.75 h40.19
  text "NSS" at 14647.9,4371.87 h40.19
  text "PB11" at 15027.42,4367.87 h40.19
  text "E5V" at 12611.59,4115.98 h46.73
  text "3V3" at 12377.59,4114.98 h46.73
  text "-" at 12649.58,4035.81 h47.07
  text "SWD" at 12377.59,4024.98 h46.73
  text "AT-START-L021 V1.0" at 13271.45,3982.42 h71.39
  text "-" at 12650.58,3943.81 h47.07
  text "SWC" at 12377.59,3934.98 h46.73
  text "RX" at 12632.64,3850.98 h46.73
  text "NRST" at 12365.53,3849.98 h46.73
  text "POWER" at 13950.93,3821.87 h40.19
  text "ANALOG IN" at 14476,3821.87 h40.19
  text "GND" at 12387.59,3758.98 h46.73
  text "TX" at 12632.64,3758.98 h46.73
  text "AN0" at 14346.68,3665.52 h45.94 r90
  text "AN1" at 14442.68,3665.52 h45.94 r90
  text "VDD" at 13752.38,3664.84 h45.94 r90
  text "AN2" at 14547.68,3664.52 h45.94 r90
  text "AN3" at 14648.68,3664.52 h45.94 r90
  text "AN4" at 14750.68,3664.52 h45.94 r90
  text "AN5" at 14850.68,3664.52 h45.94 r90
  text "5V" at 13854.38,3663.92 h45.94 r90
  text "GND" at 13953.38,3663.37 h45.94 r90
  text "GND" at 14054.67,3663.37 h45.94 r90
  text "IOREF" at 13554.38,3662.27 h45.94 r90
  text "RESET" at 13651.38,3661.27 h45.94 r90
  text "AT-Link" at 12039.59,3602.64 h57.42
  text "GND" at 15038.65,3480.71 h45.94
  text "B0" at 14439.23,3461.32 h34.45 r45
  text "B2" at 14543.23,3461.32 h34.45 r45
  text "B11" at 14643.16,3460.25 h34.45 r45
  text "A0" at 14040.56,3458.6 h34.45 r45
  text "A2" at 14134.39,3458.6 h34.45 r45
  text "A4" at 14243.51,3458.6 h34.45 r45
  text "A6" at 14340.23,3459.32 h34.45 r45
  text "F1*" at 13832.16,3458.25 h34.45 r45
  text "NC" at 13944.23,3458.32 h34.45 r45
  text "C13" at 13628.49,3450.55 h34.45 r45
  text "VDD" at 14731.16,3450.25 h34.45 r45
  text "C15*" at 13719.09,3445.18 h34.45 r45
  text "B1" at 14555.23,3166.32 h34.45 r45
  text "A1" at 14148.56,3165.11 h34.45 r45
  text "NC" at 14044.23,3163.32 h34.45 r45
  text "A5" at 14341.23,3157.32 h34.45 r45
  text "A3" at 14240.15,3155.84 h34.45 r45
  text "A7" at 14444.23,3156.32 h34.45 r45
  text "F0*" at 13836.16,3148.25 h34.45 r45
  text "B10" at 14643.16,3148.25 h34.45 r45
  text "GND" at 14736.16,3137.25 h34.45 r45
  text "C14*" at 13731.09,3135.18 h34.45 r45
  text "VDD" at 13628.16,3134.25 h34.45 r45
  text "NRST" at 13915.09,3115.18 h34.45 r45
  text "RESET" at 12417.94,3109.34 h45.94
  text "USER" at 12940.49,3108.34 h45.94
  text "23" at 14725.41,3084.76 h38.28
  text "11" at 14134.41,3082.76 h38.28
  text "1" at 13640.98,3079.91 h37.97
Bottom Silkscreen Layer:
  text "31" at 14444.38,5852 h38.28 r315
  text "41" at 13946.15,5851.4 h38.28 r315
  text "39" at 14047,5847.29 h38.28 r315
  text "37" at 14148.98,5846.73 h38.28 r315
  text "35" at 14250.96,5846.73 h38.28 r315
  text "33" at 14352.94,5846.73 h38.28 r315
  text "29" at 14545.23,5847.29 h38.28 r315
  text "27" at 14647.21,5846.73 h38.28 r315
  text "25" at 14749.19,5846.73 h38.28 r315
  text "47" at 13647.14,5846.13 h38.28 r315
  text "45" at 13750.32,5846.13 h38.28 r315
  text "43" at 13853.5,5846.13 h38.28 r315
  text "46" at 13744.26,5568.73 h38.28 r315
  text "38" at 14149.5,5568.73 h38.28 r315
  text "36" at 14248.5,5569.29 h38.28 r315
  text "32" at 14449.95,5568.73 h38.28 r315
  text "30" at 14550.07,5568.73 h38.28 r315
  text "28" at 14650.2,5568.73 h38.28 r315
  text "26" at 14749.19,5569.29 h38.28 r315
  text "48" at 13644.14,5568.13 h38.28 r315
  text "44" at 13846.72,5567.56 h38.28 r315
  text "42" at 13948.05,5568.13 h38.28 r315
  text "40" at 14049.38,5568.13 h38.28 r315
  text "34" at 14349.82,5568.13 h38.28 r315
  text "VCC" at 12267.36,5142.94 h34.45 r90
  text "AT32L021C8T7" at 14056.38,3927.28 h114.84
  text "2" at 13641.57,3456.92 h37.97 r315
  text "6" at 13835.16,3457.49 h37.97 r315
  text "8" at 13933.96,3456.92 h37.97 r315
  text "4" at 13742.5,3456.36 h37.97 r315
  text "10" at 14038.37,3447.73 h38.28 r315
  text "12" at 14140.78,3447.73 h38.28 r315
  text "16" at 14337.68,3448.29 h38.28 r315
  text "18" at 14434.09,3447.73 h38.28 r315
  text "14" at 14243.4,3447.13 h38.28 r315
  text "20" at 14540.04,3442.46 h38.28 r315
  text "22" at 14643.99,3442.46 h38.28 r315
  text "24" at 14749.14,3441.86 h38.28 r315
  text "1" at 13624.57,3198.12 h37.97 r315
  text "3" at 13730.71,3192.92 h37.97 r315
  text "5" at 13830.84,3192.92 h37.97 r315
  text "7" at 13935.98,3192.92 h37.97 r315
  text "9" at 14030.99,3193.49 h37.97 r315
  text "11" at 14127.21,3189 h38.28 r315
  text "13" at 14234.96,3183.73 h38.28 r315
  text "15" at 14336.72,3183.73 h38.28 r315
  text "17" at 14439.47,3183.73 h38.28 r315
  text "19" at 14540.09,3184.29 h38.28 r315
  text "21" at 14639.85,3183.73 h38.28 r315
  text "23" at 14750.14,3178.46 h38.28 r315
Mechanical Layer:
  circle w1 net "": c15321.58,5929.2 r62.99
  circle w1 net "": c15321.58,3154.52 r62.99
  circle w1 net "": c12130.59,3154.52 r62.99
  circle w1 net "": c12130.59,5929.2 r62.99
  circle w1 net "": c14933.35,4892.35 r62.99
  circle w1 net "": c12883.35,3592.35 r62.99
  circle w1 net "": c12933.35,5492.35 r62.99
